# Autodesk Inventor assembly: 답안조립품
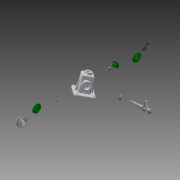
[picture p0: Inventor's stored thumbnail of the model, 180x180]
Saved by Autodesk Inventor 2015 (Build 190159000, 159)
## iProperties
Created: 2016-02
Part Number: 답안조립품
Document SubType Name: Assembly
Designer: Administrator
Author: Administrator
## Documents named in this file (19)
- C:\Users\Administrator\Desktop\460219V1006\답안조립품.iam
- C:\Users\Administrator\Desktop\460219V1006\V-벨트풀리.ipt
- C:\Users\Administrator\Desktop\460219V1006\고정핀.ipt
- C:\Users\Administrator\Desktop\460219V1006\뒤커버.ipt
- C:\Users\Administrator\Desktop\460219V1006\링크.ipt
- C:\Users\Administrator\Desktop\460219V1006\멈춤링 6 x 5.ipt
- C:\Users\Administrator\Desktop\460219V1006\멈춤링 15 x 1.ipt
- C:\Users\Administrator\Desktop\460219V1006\베어링 15 x 35 x 11.ipt
- C:\Users\Administrator\Desktop\460219V1006\본체.ipt
- C:\Users\Administrator\Desktop\460219V1006\볼트 M3 x 8.ipt
- C:\Users\Administrator\Desktop\460219V1006\볼트 M4 x 10.ipt
- C:\Users\Administrator\Desktop\460219V1006\볼트 M6 x 12.ipt
- C:\Users\Administrator\Desktop\460219V1006\상부부시.ipt
- C:\Users\Administrator\Desktop\460219V1006\슬라이드바.ipt
- C:\Users\Administrator\Desktop\460219V1006\앞커버.ipt
- C:\Users\Administrator\Desktop\460219V1006\오일실 15 25 7.ipt
- C:\Users\Administrator\Desktop\460219V1006\와셔.ipt
- C:\Users\Administrator\Desktop\460219V1006\키 5 x 5 x 14.ipt
- C:\Users\Administrator\Desktop\460219V1006\편심축.ipt
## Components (5 placed, 5 different names)
1. V-벨트풀리:1
2. 고정핀:1
3. ISO 4762 M3 x 8:1
4. ISO 4762 M4 x 10:1
5. ISO 4018 M6 x 12:1
